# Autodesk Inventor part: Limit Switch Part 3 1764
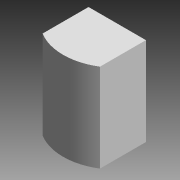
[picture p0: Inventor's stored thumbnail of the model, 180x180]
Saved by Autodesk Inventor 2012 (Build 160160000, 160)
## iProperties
Shininess: 0.0
Created: 2002-01
Part Number: Limit Switch Part 3 1764
Document SubType Name: Modeling
Density: 1 g/cm^3
Material: Default
Density: 0.0
Volumn: 0.0
Area: 0.0
PropertySet Name: Model Information
Control State: 0
Master: False
Checked Out: False
Author: Administrator
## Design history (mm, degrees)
node "Base1"
body "Solid1"
